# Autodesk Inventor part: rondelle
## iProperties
Author: robert
Shininess: 20.0
Angle Display Precision: 2
Document Length Units: 11269
Document Angle Units: 11283
Document Time Units: 11279
Document Mass Units: 11290
Document Length Units Precision: 3
Document Angle Units Precision: 2
Compacted: True
PropertySet Name: _Private Model Information
Created: 2002-09
Part Number: rondelle
Material: Par défaut
Document SubType Name: Modélisation
Designer: robert
Control State: 0
Master: False
Checked Out: False
PropertySet Name: Design Tracking Control
Density: 0.0
Volumn: 0.0
Area: 0.0
PropertySet Name: Model Information
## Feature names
1. Extrusion1
